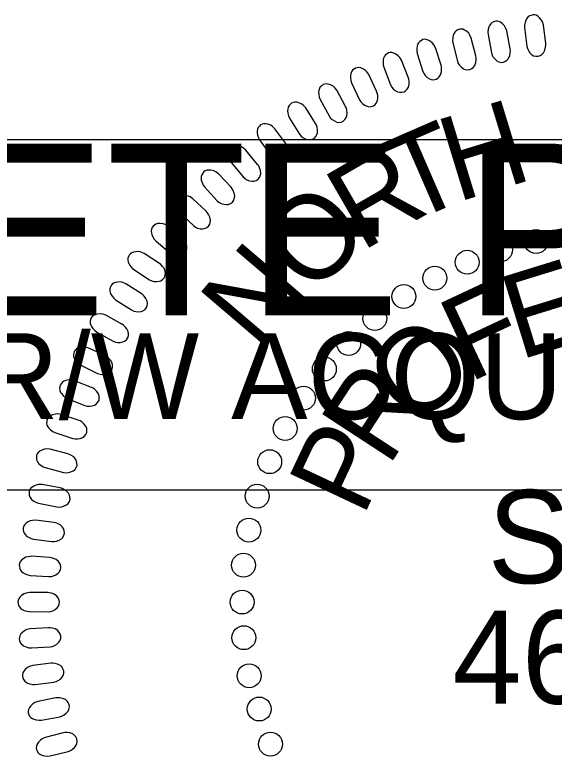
# Model space of a CAD drawing. Extents: x 497599 to 513368, y 404140 to 476034.
# Drawn here: x 507268.47 to 507304.65, y 439737.1 to 439786.79 of the extents above; entities that cross this region are included whole.
import ezdxf

# ---------------------------------------------------------------- set-up
doc = ezdxf.new("R2010")
doc.units = 0
doc.layers.add('Sheet PE Seal Cell', color=7, linetype='Continuous')
doc.layers.add('Sheet Sticker Incomplete CELL', color=7, linetype='Continuous')

msp = doc.modelspace()

# ---------------------------------------------------------------- linework, layer by layer
at = {"layer": 'Sheet PE Seal Cell'}
for points in [[(507304.079, 439784.876), (507303.926, 439786.093), (507303.861, 439786.306), (507303.792, 439786.438), (507303.659, 439786.592), (507303.549, 439786.689), (507303.428, 439786.754), (507303.319, 439786.78), (507303.205, 439786.786), (507303.097, 439786.752), (507302.982, 439786.708), (507302.886, 439786.636), (507302.794, 439786.523), (507302.745, 439786.437), (507302.697, 439786.28), (507302.66, 439786.094), (507302.657, 439785.933), (507302.807, 439784.686), (507302.851, 439784.52), (507302.913, 439784.387), (507303.021, 439784.24), (507303.15, 439784.116), (507303.257, 439784.049), (507303.42, 439784.008), (507303.571, 439784.007), (507303.714, 439784.066), (507303.812, 439784.129), (507303.925, 439784.243), (507304.023, 439784.426), (507304.067, 439784.613), (507304.08, 439784.745)], [(507301.698, 439784.508), (507301.469, 439785.712), (507301.391, 439785.921), (507301.314, 439786.049), (507301.171, 439786.194), (507301.056, 439786.284), (507300.931, 439786.341), (507300.82, 439786.361), (507300.706, 439786.36), (507300.6, 439786.319), (507300.488, 439786.267), (507300.396, 439786.189), (507300.312, 439786.071), (507300.268, 439785.982), (507300.23, 439785.822), (507300.205, 439785.635), (507300.213, 439785.474), (507300.441, 439784.238), (507300.494, 439784.075), (507300.564, 439783.947), (507300.683, 439783.807), (507300.819, 439783.69), (507300.929, 439783.63), (507301.095, 439783.601), (507301.245, 439783.61), (507301.385, 439783.677), (507301.478, 439783.745), (507301.584, 439783.867), (507301.67, 439784.056), (507301.702, 439784.245), (507301.707, 439784.377)], [(507299.392, 439784.036), (507299.088, 439785.224), (507298.997, 439785.427), (507298.912, 439785.55), (507298.761, 439785.686), (507298.64, 439785.768), (507298.512, 439785.817), (507298.4, 439785.831), (507298.286, 439785.822), (507298.183, 439785.775), (507298.075, 439785.716), (507297.988, 439785.632), (507297.911, 439785.509), (507297.873, 439785.417), (507297.845, 439785.255), (507297.832, 439785.067), (507297.849, 439784.907), (507298.155, 439783.688), (507298.218, 439783.529), (507298.297, 439783.405), (507298.423, 439783.272), (507298.566, 439783.165), (507298.68, 439783.112), (507298.848, 439783.092), (507298.997, 439783.111), (507299.132, 439783.186), (507299.221, 439783.26), (507299.319, 439783.389), (507299.393, 439783.583), (507299.414, 439783.774), (507299.41, 439783.906)], [(507297.059, 439783.415), (507296.68, 439784.582), (507296.577, 439784.779), (507296.484, 439784.895), (507296.326, 439785.022), (507296.199, 439785.097), (507296.068, 439785.138), (507295.956, 439785.144), (507295.843, 439785.128), (507295.742, 439785.075), (507295.639, 439785.009), (507295.557, 439784.92), (507295.488, 439784.793), (507295.456, 439784.698), (507295.438, 439784.535), (507295.437, 439784.346), (507295.464, 439784.187), (507295.845, 439782.99), (507295.919, 439782.836), (507296.005, 439782.717), (507296.139, 439782.592), (507296.289, 439782.494), (507296.406, 439782.448), (507296.574, 439782.44), (507296.722, 439782.467), (507296.852, 439782.551), (507296.937, 439782.631), (507297.027, 439782.765), (507297.088, 439782.963), (507297.096, 439783.155), (507297.085, 439783.287)], [(507294.858, 439782.599), (507294.407, 439783.74), (507294.291, 439783.93), (507294.192, 439784.04), (507294.025, 439784.157), (507293.894, 439784.223), (507293.761, 439784.256), (507293.649, 439784.255), (507293.537, 439784.231), (507293.44, 439784.172), (507293.34, 439784.1), (507293.264, 439784.006), (507293.204, 439783.875), (507293.178, 439783.779), (507293.17, 439783.615), (507293.181, 439783.426), (507293.218, 439783.269), (507293.674, 439782.098), (507293.757, 439781.949), (507293.85, 439781.835), (507293.992, 439781.72), (507294.147, 439781.631), (507294.267, 439781.592), (507294.436, 439781.595), (507294.582, 439781.632), (507294.706, 439781.724), (507294.785, 439781.808), (507294.867, 439781.948), (507294.916, 439782.149), (507294.912, 439782.341), (507294.892, 439782.473)], [(507292.741, 439781.666), (507292.219, 439782.776), (507292.092, 439782.958), (507291.985, 439783.063), (507291.812, 439783.169), (507291.677, 439783.226), (507291.541, 439783.251), (507291.43, 439783.242), (507291.32, 439783.213), (507291.227, 439783.147), (507291.131, 439783.069), (507291.062, 439782.971), (507291.009, 439782.836), (507290.99, 439782.738), (507290.992, 439782.574), (507291.015, 439782.386), (507291.062, 439782.232), (507291.59, 439781.092), (507291.682, 439780.948), (507291.783, 439780.841), (507291.932, 439780.735), (507292.093, 439780.656), (507292.214, 439780.625), (507292.382, 439780.638), (507292.526, 439780.683), (507292.644, 439780.783), (507292.717, 439780.873), (507292.79, 439781.017), (507292.826, 439781.221), (507292.811, 439781.412), (507292.783, 439781.542)], [(507290.658, 439780.652), (507290.067, 439781.727), (507289.929, 439781.902), (507289.816, 439781.999), (507289.636, 439782.093), (507289.498, 439782.143), (507289.361, 439782.159), (507289.251, 439782.143), (507289.142, 439782.107), (507289.054, 439782.036), (507288.963, 439781.952), (507288.9, 439781.849), (507288.857, 439781.711), (507288.843, 439781.612), (507288.855, 439781.449), (507288.89, 439781.262), (507288.947, 439781.112), (507289.545, 439780.007), (507289.646, 439779.869), (507289.753, 439779.768), (507289.908, 439779.672), (507290.074, 439779.603), (507290.197, 439779.58), (507290.364, 439779.603), (507290.504, 439779.658), (507290.616, 439779.764), (507290.684, 439779.858), (507290.748, 439780.007), (507290.77, 439780.213), (507290.743, 439780.403), (507290.707, 439780.531)], [(507288.64, 439779.51), (507287.983, 439780.546), (507287.834, 439780.711), (507287.716, 439780.801), (507287.53, 439780.885), (507287.389, 439780.925), (507287.252, 439780.932), (507287.142, 439780.91), (507287.037, 439780.866), (507286.952, 439780.79), (507286.868, 439780.7), (507286.811, 439780.594), (507286.776, 439780.454), (507286.768, 439780.354), (507286.792, 439780.192), (507286.838, 439780.008), (507286.904, 439779.861), (507287.571, 439778.796), (507287.68, 439778.665), (507287.793, 439778.571), (507287.954, 439778.484), (507288.123, 439778.427), (507288.248, 439778.411), (507288.413, 439778.445), (507288.55, 439778.508), (507288.655, 439778.621), (507288.717, 439778.72), (507288.771, 439778.872), (507288.781, 439779.079), (507288.741, 439779.267), (507288.697, 439779.392)], [(507286.64, 439778.155), (507285.919, 439779.148), (507285.76, 439779.304), (507285.636, 439779.386), (507285.445, 439779.457), (507285.302, 439779.489), (507285.165, 439779.487), (507285.056, 439779.458), (507284.954, 439779.408), (507284.875, 439779.327), (507284.796, 439779.232), (507284.746, 439779.123), (507284.72, 439778.98), (507284.718, 439778.88), (507284.752, 439778.719), (507284.809, 439778.539), (507284.885, 439778.397), (507285.617, 439777.376), (507285.735, 439777.252), (507285.853, 439777.165), (507286.019, 439777.088), (507286.192, 439777.041), (507286.318, 439777.034), (507286.48, 439777.078), (507286.612, 439777.15), (507286.71, 439777.27), (507286.765, 439777.371), (507286.81, 439777.527), (507286.807, 439777.734), (507286.756, 439777.919), (507286.704, 439778.042)], [(507284.759, 439776.766), (507283.977, 439777.712), (507283.809, 439777.857), (507283.68, 439777.931), (507283.485, 439777.99), (507283.341, 439778.013), (507283.203, 439778.003), (507283.097, 439777.967), (507282.998, 439777.911), (507282.924, 439777.824), (507282.852, 439777.725), (507282.808, 439777.612), (507282.792, 439777.468), (507282.796, 439777.369), (507282.84, 439777.21), (507282.908, 439777.034), (507282.993, 439776.896), (507283.787, 439775.924), (507283.913, 439775.807), (507284.036, 439775.728), (507284.207, 439775.663), (507284.382, 439775.627), (507284.508, 439775.627), (507284.667, 439775.681), (507284.795, 439775.761), (507284.884, 439775.887), (507284.934, 439775.992), (507284.968, 439776.149), (507284.952, 439776.356), (507284.889, 439776.537), (507284.83, 439776.657)], [(507282.972, 439775.227), (507282.132, 439776.122), (507281.955, 439776.256), (507281.821, 439776.323), (507281.623, 439776.369), (507281.478, 439776.383), (507281.341, 439776.364), (507281.237, 439776.322), (507281.142, 439776.26), (507281.074, 439776.168), (507281.007, 439776.064), (507280.971, 439775.949), (507280.964, 439775.805), (507280.974, 439775.706), (507281.028, 439775.551), (507281.107, 439775.379), (507281.199, 439775.248), (507282.055, 439774.326), (507282.187, 439774.217), (507282.315, 439774.147), (507282.489, 439774.092), (507282.667, 439774.066), (507282.793, 439774.074), (507282.948, 439774.138), (507283.071, 439774.227), (507283.152, 439774.358), (507283.195, 439774.466), (507283.219, 439774.625), (507283.191, 439774.83), (507283.116, 439775.008), (507283.05, 439775.122)], [(507281.309, 439773.618), (507280.415, 439774.458), (507280.23, 439774.581), (507280.092, 439774.638), (507279.892, 439774.673), (507279.745, 439774.677), (507279.61, 439774.65), (507279.51, 439774.601), (507279.418, 439774.533), (507279.356, 439774.438), (507279.296, 439774.33), (507279.268, 439774.213), (507279.269, 439774.068), (507279.286, 439773.97), (507279.349, 439773.818), (507279.439, 439773.652), (507279.539, 439773.526), (507280.45, 439772.66), (507280.589, 439772.561), (507280.722, 439772.498), (507280.9, 439772.454), (507281.078, 439772.44), (507281.203, 439772.456), (507281.354, 439772.529), (507281.471, 439772.625), (507281.544, 439772.761), (507281.579, 439772.871), (507281.594, 439773.033), (507281.552, 439773.236), (507281.467, 439773.408), (507281.393, 439773.518)], [(507279.696, 439771.831), (507278.751, 439772.613), (507278.558, 439772.724), (507278.417, 439772.773), (507278.215, 439772.795), (507278.069, 439772.79), (507277.936, 439772.754), (507277.839, 439772.699), (507277.751, 439772.625), (507277.695, 439772.527), (507277.643, 439772.415), (507277.621, 439772.297), (507277.632, 439772.152), (507277.655, 439772.055), (507277.727, 439771.908), (507277.827, 439771.747), (507277.936, 439771.629), (507278.899, 439770.822), (507279.044, 439770.731), (507279.18, 439770.676), (507279.36, 439770.644), (507279.539, 439770.641), (507279.663, 439770.666), (507279.809, 439770.748), (507279.919, 439770.85), (507279.984, 439770.991), (507280.012, 439771.103), (507280.017, 439771.265), (507279.962, 439771.465), (507279.867, 439771.631), (507279.786, 439771.737)], [(507278.171, 439770.129), (507277.141, 439770.795), (507276.936, 439770.882), (507276.791, 439770.914), (507276.587, 439770.912), (507276.443, 439770.89), (507276.315, 439770.839), (507276.225, 439770.773), (507276.147, 439770.689), (507276.103, 439770.584), (507276.064, 439770.468), (507276.056, 439770.348), (507276.084, 439770.205), (507276.118, 439770.112), (507276.207, 439769.974), (507276.326, 439769.826), (507276.447, 439769.721), (507277.499, 439769.033), (507277.653, 439768.959), (507277.795, 439768.922), (507277.978, 439768.91), (507278.155, 439768.929), (507278.275, 439768.967), (507278.411, 439769.067), (507278.508, 439769.181), (507278.556, 439769.328), (507278.571, 439769.443), (507278.557, 439769.604), (507278.479, 439769.796), (507278.365, 439769.951), (507278.272, 439770.046)], [(507276.957, 439768.106), (507275.922, 439768.764), (507275.716, 439768.85), (507275.571, 439768.881), (507275.367, 439768.877), (507275.222, 439768.854), (507275.095, 439768.802), (507275.005, 439768.735), (507274.928, 439768.651), (507274.885, 439768.545), (507274.846, 439768.428), (507274.84, 439768.308), (507274.869, 439768.166), (507274.904, 439768.073), (507274.994, 439767.935), (507275.113, 439767.789), (507275.236, 439767.685), (507276.293, 439767.005), (507276.448, 439766.933), (507276.59, 439766.896), (507276.773, 439766.886), (507276.951, 439766.906), (507277.07, 439766.945), (507277.205, 439767.046), (507277.302, 439767.161), (507277.348, 439767.308), (507277.362, 439767.424), (507277.346, 439767.585), (507277.267, 439767.776), (507277.152, 439767.929), (507277.058, 439768.024)], [(507275.654, 439766.057), (507274.578, 439766.648), (507274.369, 439766.721), (507274.221, 439766.743), (507274.018, 439766.726), (507273.875, 439766.694), (507273.751, 439766.635), (507273.666, 439766.562), (507273.594, 439766.473), (507273.558, 439766.365), (507273.526, 439766.246), (507273.528, 439766.126), (507273.565, 439765.986), (507273.606, 439765.895), (507273.705, 439765.764), (507273.833, 439765.625), (507273.963, 439765.528), (507275.06, 439764.916), (507275.219, 439764.854), (507275.363, 439764.826), (507275.546, 439764.828), (507275.723, 439764.859), (507275.839, 439764.906), (507275.968, 439765.014), (507276.057, 439765.136), (507276.094, 439765.286), (507276.101, 439765.401), (507276.075, 439765.561), (507275.984, 439765.747), (507275.859, 439765.893), (507275.76, 439765.981)], [(507274.545, 439763.933), (507273.435, 439764.456), (507273.22, 439764.516), (507273.072, 439764.528), (507272.871, 439764.499), (507272.73, 439764.457), (507272.61, 439764.39), (507272.529, 439764.312), (507272.464, 439764.219), (507272.434, 439764.109), (507272.41, 439763.988), (507272.419, 439763.869), (507272.465, 439763.731), (507272.512, 439763.643), (507272.619, 439763.518), (507272.756, 439763.387), (507272.89, 439763.299), (507274.025, 439762.757), (507274.187, 439762.705), (507274.332, 439762.687), (507274.515, 439762.7), (507274.689, 439762.742), (507274.802, 439762.795), (507274.924, 439762.912), (507275.005, 439763.039), (507275.032, 439763.191), (507275.032, 439763.307), (507274.996, 439763.464), (507274.894, 439763.645), (507274.76, 439763.782), (507274.655, 439763.864)], [(507273.605, 439761.814), (507272.465, 439762.266), (507272.247, 439762.312), (507272.098, 439762.315), (507271.899, 439762.273), (507271.761, 439762.223), (507271.646, 439762.148), (507271.571, 439762.065), (507271.51, 439761.969), (507271.488, 439761.857), (507271.472, 439761.735), (507271.488, 439761.616), (507271.543, 439761.482), (507271.595, 439761.397), (507271.709, 439761.279), (507271.854, 439761.158), (507271.994, 439761.078), (507273.159, 439760.608), (507273.325, 439760.567), (507273.472, 439760.557), (507273.653, 439760.581), (507273.824, 439760.634), (507273.934, 439760.695), (507274.048, 439760.819), (507274.121, 439760.95), (507274.139, 439761.104), (507274.131, 439761.22), (507274.086, 439761.375), (507273.972, 439761.548), (507273.829, 439761.677), (507273.72, 439761.753)], [(507272.73, 439759.625), (507271.563, 439760.004), (507271.343, 439760.036), (507271.193, 439760.031), (507270.998, 439759.976), (507270.863, 439759.917), (507270.753, 439759.835), (507270.683, 439759.749), (507270.629, 439759.648), (507270.614, 439759.535), (507270.605, 439759.412), (507270.629, 439759.295), (507270.691, 439759.164), (507270.749, 439759.082), (507270.871, 439758.972), (507271.023, 439758.86), (507271.168, 439758.789), (507272.36, 439758.393), (507272.528, 439758.362), (507272.675, 439758.362), (507272.855, 439758.397), (507273.022, 439758.461), (507273.128, 439758.528), (507273.234, 439758.659), (507273.299, 439758.795), (507273.307, 439758.95), (507273.292, 439759.064), (507273.237, 439759.217), (507273.112, 439759.383), (507272.962, 439759.502), (507272.848, 439759.571)], [(507272.025, 439757.369), (507270.837, 439757.675), (507270.615, 439757.693), (507270.467, 439757.678), (507270.275, 439757.611), (507270.144, 439757.544), (507270.039, 439757.456), (507269.974, 439757.364), (507269.927, 439757.26), (507269.918, 439757.147), (507269.918, 439757.023), (507269.949, 439756.907), (507270.02, 439756.781), (507270.082, 439756.703), (507270.211, 439756.601), (507270.37, 439756.499), (507270.518, 439756.437), (507271.734, 439756.117), (507271.904, 439756.096), (507272.05, 439756.105), (507272.227, 439756.152), (507272.39, 439756.226), (507272.491, 439756.3), (507272.589, 439756.437), (507272.645, 439756.577), (507272.643, 439756.732), (507272.621, 439756.846), (507272.556, 439756.994), (507272.422, 439757.151), (507272.265, 439757.261), (507272.146, 439757.322)], [(507271.514, 439755.074), (507270.309, 439755.304), (507270.087, 439755.308), (507269.939, 439755.284), (507269.751, 439755.205), (507269.626, 439755.13), (507269.526, 439755.035), (507269.468, 439754.94), (507269.427, 439754.834), (507269.426, 439754.72), (507269.433, 439754.597), (507269.471, 439754.483), (507269.55, 439754.361), (507269.617, 439754.287), (507269.751, 439754.193), (507269.917, 439754.1), (507270.069, 439754.049), (507271.302, 439753.805), (507271.473, 439753.796), (507271.618, 439753.814), (507271.792, 439753.872), (507271.95, 439753.955), (507272.046, 439754.036), (507272.135, 439754.179), (507272.183, 439754.322), (507272.171, 439754.477), (507272.142, 439754.589), (507272.068, 439754.732), (507271.924, 439754.882), (507271.76, 439754.981), (507271.638, 439755.035)], [(507271.094, 439752.759), (507269.876, 439752.913), (507269.654, 439752.904), (507269.509, 439752.87), (507269.327, 439752.78), (507269.205, 439752.698), (507269.112, 439752.596), (507269.06, 439752.497), (507269.026, 439752.388), (507269.032, 439752.275), (507269.046, 439752.152), (507269.092, 439752.041), (507269.179, 439751.925), (507269.25, 439751.855), (507269.39, 439751.77), (507269.56, 439751.688), (507269.716, 439751.645), (507270.962, 439751.48), (507271.133, 439751.481), (507271.277, 439751.508), (507271.446, 439751.577), (507271.599, 439751.671), (507271.69, 439751.758), (507271.769, 439751.905), (507271.808, 439752.052), (507271.787, 439752.205), (507271.751, 439752.315), (507271.668, 439752.453), (507271.514, 439752.593), (507271.345, 439752.683), (507271.22, 439752.728)], [(507270.807, 439750.415), (507269.583, 439750.493), (507269.361, 439750.469), (507269.218, 439750.426), (507269.042, 439750.325), (507268.926, 439750.235), (507268.84, 439750.128), (507268.793, 439750.026), (507268.766, 439749.915), (507268.78, 439749.802), (507268.802, 439749.681), (507268.855, 439749.573), (507268.948, 439749.462), (507269.024, 439749.397), (507269.169, 439749.321), (507269.344, 439749.25), (507269.502, 439749.217), (507270.756, 439749.13), (507270.926, 439749.142), (507271.068, 439749.178), (507271.233, 439749.258), (507271.38, 439749.36), (507271.466, 439749.452), (507271.535, 439749.605), (507271.564, 439749.754), (507271.534, 439749.905), (507271.491, 439750.013), (507271.4, 439750.146), (507271.238, 439750.276), (507271.063, 439750.355), (507270.935, 439750.392)], [(507270.677, 439748.064), (507269.45, 439748.065), (507269.231, 439748.027), (507269.091, 439747.976), (507268.922, 439747.863), (507268.812, 439747.766), (507268.732, 439747.654), (507268.692, 439747.55), (507268.672, 439747.437), (507268.692, 439747.325), (507268.722, 439747.206), (507268.781, 439747.101), (507268.882, 439746.996), (507268.961, 439746.936), (507269.111, 439746.869), (507269.29, 439746.809), (507269.45, 439746.787), (507270.707, 439746.779), (507270.876, 439746.801), (507271.016, 439746.846), (507271.175, 439746.936), (507271.315, 439747.048), (507271.395, 439747.145), (507271.455, 439747.302), (507271.475, 439747.452), (507271.434, 439747.601), (507271.385, 439747.705), (507271.286, 439747.833), (507271.116, 439747.953), (507270.936, 439748.02), (507270.806, 439748.05)], [(507270.73, 439745.707), (507269.505, 439745.631), (507269.289, 439745.579), (507269.152, 439745.519), (507268.99, 439745.396), (507268.886, 439745.292), (507268.814, 439745.175), (507268.781, 439745.069), (507268.768, 439744.955), (507268.795, 439744.845), (507268.833, 439744.727), (507268.898, 439744.626), (507269.005, 439744.528), (507269.088, 439744.473), (507269.241, 439744.416), (507269.424, 439744.367), (507269.584, 439744.355), (507270.839, 439744.426), (507271.008, 439744.459), (507271.143, 439744.512), (507271.297, 439744.612), (507271.43, 439744.733), (507271.503, 439744.834), (507271.554, 439744.995), (507271.564, 439745.145), (507271.515, 439745.292), (507271.458, 439745.394), (507271.351, 439745.514), (507271.175, 439745.623), (507270.991, 439745.679), (507270.859, 439745.7)], [(507270.894, 439743.326), (507269.677, 439743.173), (507269.464, 439743.108), (507269.332, 439743.039), (507269.178, 439742.906), (507269.081, 439742.796), (507269.016, 439742.675), (507268.99, 439742.566), (507268.984, 439742.452), (507269.018, 439742.344), (507269.062, 439742.229), (507269.134, 439742.132), (507269.247, 439742.041), (507269.334, 439741.991), (507269.49, 439741.943), (507269.676, 439741.907), (507269.837, 439741.904), (507271.085, 439742.054), (507271.25, 439742.097), (507271.383, 439742.16), (507271.53, 439742.268), (507271.654, 439742.396), (507271.722, 439742.503), (507271.761, 439742.667), (507271.762, 439742.817), (507271.704, 439742.961), (507271.641, 439743.058), (507271.527, 439743.172), (507271.344, 439743.269), (507271.157, 439743.313), (507271.024, 439743.327)], [(507271.228, 439741), (507270.022, 439740.771), (507269.814, 439740.693), (507269.686, 439740.616), (507269.541, 439740.474), (507269.451, 439740.358), (507269.394, 439740.233), (507269.374, 439740.123), (507269.376, 439740.009), (507269.416, 439739.903), (507269.468, 439739.791), (507269.546, 439739.699), (507269.664, 439739.615), (507269.753, 439739.571), (507269.913, 439739.533), (507270.101, 439739.507), (507270.261, 439739.515), (507271.497, 439739.743), (507271.659, 439739.797), (507271.788, 439739.867), (507271.928, 439739.985), (507272.045, 439740.121), (507272.105, 439740.232), (507272.134, 439740.397), (507272.126, 439740.548), (507272.059, 439740.687), (507271.99, 439740.781), (507271.868, 439740.887), (507271.68, 439740.972), (507271.49, 439741.005), (507271.358, 439741.01)], [(507271.707, 439738.659), (507270.519, 439738.355), (507270.316, 439738.264), (507270.193, 439738.179), (507270.057, 439738.028), (507269.974, 439737.906), (507269.925, 439737.778), (507269.913, 439737.667), (507269.921, 439737.553), (507269.968, 439737.45), (507270.027, 439737.342), (507270.111, 439737.255), (507270.234, 439737.178), (507270.326, 439737.14), (507270.487, 439737.112), (507270.676, 439737.099), (507270.836, 439737.117), (507272.055, 439737.421), (507272.214, 439737.485), (507272.338, 439737.563), (507272.47, 439737.69), (507272.578, 439737.833), (507272.631, 439737.947), (507272.65, 439738.114), (507272.632, 439738.264), (507272.556, 439738.399), (507272.482, 439738.488), (507272.354, 439738.587), (507272.16, 439738.659), (507271.969, 439738.681), (507271.836, 439738.677)]]:
    msp.add_lwpolyline(points, close=True, dxfattribs=at)
for centre in [(507303.432, 439771.594), (507301.043, 439771.037), (507298.813, 439770.201), (507296.639, 439769.141), (507294.568, 439767.906), (507292.617, 439766.433), (507290.864, 439764.76), (507289.232, 439763.048), (507287.837, 439761.096), (507286.603, 439759.065), (507285.567, 439756.835), (507284.73, 439754.524), (507284.172, 439752.254), (507283.813, 439749.903), (507283.716, 439747.429), (507283.835, 439745.039), (507284.192, 439742.489), (507284.868, 439740.258), (507285.624, 439737.907)]:
    msp.add_circle(centre, 0.801, dxfattribs=at)
at = {"layer": 'Sheet Sticker Incomplete CELL'}
msp.add_lwpolyline([(507185.195, 439754.938), (507185.195, 439778.438), (507332.195, 439778.438), (507332.195, 439754.938)], close=True, dxfattribs=at)

# ---------------------------------------------------------------- texts
at = {"layer": 'Sheet PE Seal Cell'}
for s, height, rotation, p in [('H', 5.669, 17.0557, (507298.102, 439774.199)), ('T', 5.669, 23.5451, (507294.923, 439772.789)), ('R', 5.669, 30.0345, (507291.702, 439770.87)), ('O', 5.669, 43.0132, (507288.227, 439767.842)), ('N', 5.669, 49.5025, (507284.88, 439764.086)), ('E', 5.669, 17.1686, (507302.299, 439763.63)), ('F', 5.669, 25.1084, (507298.909, 439762.091)), ('O', 5.669, 40.988, (507295.212, 439758.952)), ('R', 5.669, 56.8676, (507293.498, 439756.406)), ('P', 5.669, 64.8074, (507291.811, 439753.044)), ('SEAL', 6.2363, 359.9814, (507300.182, 439748.695)), ('46155', 6.2363, 359.9814, (507297.834, 439740.617))]:
    msp.add_text(s, height=height, rotation=rotation, dxfattribs=at).set_placement(p)
at = {"layer": 'Sheet Sticker Incomplete CELL'}
for s, height, p in [('INCOMPLETE PLANS', 11.52, (507194.145, 439766.638)), ('DO NOT USE FOR R/W ACQUISITION', 5.76, (507197.395, 439759.688))]:
    msp.add_text(s, height=height, dxfattribs=at).set_placement(p)

doc.saveas('drawing.dxf')
